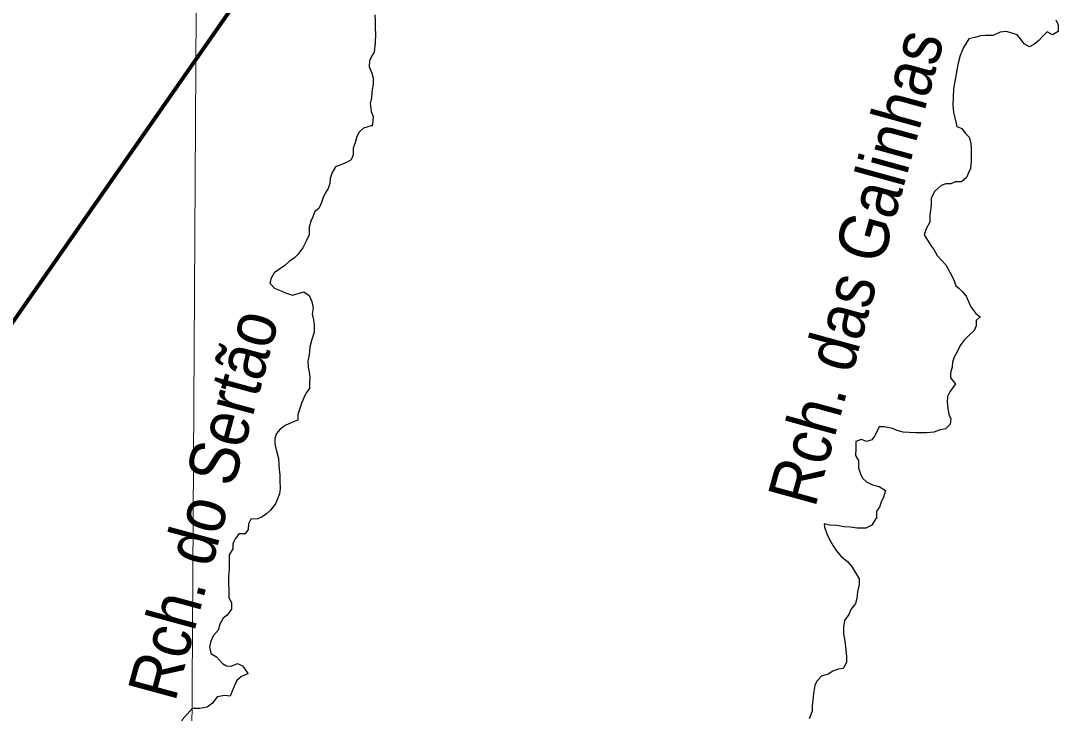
# Model space of a CAD drawing. Extents: x 553962 to 842807, y 8883888 to 9032388.
# Drawn here: x 717768 to 728228, y 8938163 to 8945147 of the extents above; entities that cross this region are included whole.
import ezdxf
from ezdxf.enums import TextEntityAlignment as Align

# ---------------------------------------------------------------- set-up
doc = ezdxf.new("R2010")
doc.units = 0
doc.header["$LTSCALE"] = 200
for name, color, linetype, lineweight in [('1', 7, 'Continuous', 13), ('24', 7, 'Continuous', 25), ('28', 7, 'Continuous', 40)]:
    doc.layers.add(name, color=color, linetype=linetype, lineweight=lineweight)
doc.layers.add('49', color=7, linetype='Continuous')

msp = doc.modelspace()

# ---------------------------------------------------------------- linework, layer by layer
at = {"layer": '1'}
msp.add_lwpolyline([(719978.9, 9023574.5), (719561.6, 8949232.2), (719215.6, 8890710.6)], dxfattribs=at)
at = {"layer": '24'}
for points in [[(728203.3, 8945156.8), (728228.4, 8945105.7), (728228, 8945039.5), (728171.8, 8945004.2), (728116, 8945035.1), (728069.9, 8944989.6), (728034.1, 8944949), (727982.9, 8944908.6), (727937, 8944883.4), (727886.3, 8944914.3), (727851, 8944960.3), (727815.8, 8945006.4), (727765, 8945022), (727704.1, 8945037.6), (727643, 8945032.9), (727571.6, 8944997.7), (727495.3, 8944998.2), (727444.4, 8944993.4), (727388.3, 8944978.4), (727327.2, 8944963.6), (727273, 8944875.7), (727239.5, 8944797.4), (727239.5, 8944797.4), (727217.1, 8944704.3), (727172.4, 8944462.1)], [(721333.1, 8944831.8), (721314, 8944802.2), (721283.1, 8944746.3), (721282.7, 8944685.2), (721307.7, 8944618.9), (721322.6, 8944567.9), (721322.1, 8944506.8), (721306.3, 8944425.4), (721305.9, 8944369.4), (721290.3, 8944313.4), (721299.9, 8944231.9), (721319.9, 8944180.8), (721319.5, 8944129.9), (721309.9, 8944083.2)], [(727172.4, 8944462.1), (727164.9, 8944294.4), (727172.4, 8944223.6), (727194.7, 8944123), (727205.5, 8944081.4), (727256.2, 8944060.7), (727291.5, 8944014.6), (727331.9, 8943973.7), (727346.8, 8943912.4), (727351.5, 8943856.4), (727351.1, 8943800.4), (727350.6, 8943729.1), (727345, 8943657.8), (727324.3, 8943612.1), (727303.7, 8943566.4), (727252.5, 8943520.9), (727191.5, 8943521.3), (727145.6, 8943501.2), (727094.7, 8943501.5), (727048.8, 8943486.5), (726982.3, 8943425.8), (726946.2, 8943354.7), (726945.7, 8943288.5), (726940.3, 8943237.7), (726934.9, 8943186.8), (726934.4, 8943115.5), (726898.3, 8943049.5), (726877.6, 8942988.5), (726942.9, 8942881.2), (726973.2, 8942840.2), (727008.3, 8942778.9), (727094.2, 8942686.7), (727159.5, 8942569.2), (727179.5, 8942523.2), (727194.4, 8942472.2)], [(721311.4, 8944090.8), (721222.4, 8944064.3), (721181.5, 8944023.8), (721155.7, 8943978.2), (721140.1, 8943917.2), (721119.3, 8943861.3), (721118.9, 8943795.1), (721098.2, 8943744.3), (721052.2, 8943719.1), (720996.1, 8943694), (720940, 8943673.9), (720909.1, 8943618.1), (720888.3, 8943557.1), (720882.9, 8943506.2), (720867.3, 8943455.4), (720836.5, 8943409.8), (720815.8, 8943364.1), (720800.2, 8943313.2), (720774.3, 8943252.3), (720733.5, 8943222), (720712.8, 8943171.2), (720692.1, 8943125.5), (720676.4, 8943064.5), (720675.9, 8942988.1), (720650.1, 8942932.2), (720613.9, 8942856.1), (720562.6, 8942790.2), (720526.8, 8942754.7), (720475.7, 8942719.4), (720429.6, 8942678.9), (720368.3, 8942633.5), (720322.3, 8942603.2), (720291.4, 8942552.5), (720280.9, 8942501.6), (720326.3, 8942450.4), (720377, 8942429.8), (720437.9, 8942403.9), (720508.9, 8942378), (720565, 8942398), (720621, 8942413), (720676.7, 8942377), (720701.7, 8942315.7), (720716.5, 8942249.4), (720706, 8942188.4), (720720.8, 8942132.3), (720725.5, 8942076.2), (720725, 8942004.9), (720704.2, 8941933.8), (720683.3, 8941857.5), (720677.7, 8941776.1), (720662, 8941715.1), (720666.7, 8941653.9), (720676.5, 8941602.9), (720681.2, 8941552), (720680.8, 8941501.1), (720680.4, 8941440), (720644.5, 8941394.3), (720623.8, 8941343.6), (720603.2, 8941297.8), (720582.4, 8941236.9), (720561.6, 8941175.9), (720561.2, 8941119.9), (720500, 8941094.8), (720433.7, 8941064.6), (720382.6, 8941029.3), (720346.7, 8940983.7), (720331.1, 8940932.9), (720330.7, 8940881.9), (720345.5, 8940805.5), (720365.3, 8940734), (720370, 8940672.9), (720374.7, 8940621.9), (720379.4, 8940565.9), (720379, 8940509.9), (720383.5, 8940428.4), (720378.1, 8940377.5), (720336.7, 8940275.9), (720285.4, 8940210), (720244.5, 8940174.6), (720203.6, 8940144.3), (720157.6, 8940124.2), (720086.4, 8940119.6), (720065.7, 8940073.9), (720060.3, 8940017.9), (720029.4, 8939972.2), (719968.4, 8939972.6), (719932.5, 8939927), (719906.7, 8939876.2), (719906.3, 8939820.2), (719870.3, 8939759.3), (719869.9, 8939703.3), (719869.3, 8939611.7), (719863.7, 8939545.5), (719863.2, 8939464), (719867.9, 8939408), (719867.3, 8939326.5), (719892.4, 8939280.5), (719892, 8939214.3), (719850.8, 8939153.5), (719810, 8939123.2), (719773.9, 8939062.3)], [(727194.4, 8942472.2), (727224.8, 8942451.7), (727260.1, 8942415.8), (727300.5, 8942369.7), (727345.5, 8942262.5), (727395.9, 8942196), (727441.4, 8942160.1), (727443.2, 8942160.1)], [(727441.4, 8942160.1), (727400.5, 8942124.7), (727400.1, 8942068.7), (727379.5, 8942023), (727328.2, 8941972.3), (727277, 8941921.7), (727241.1, 8941871), (727205, 8941800), (727179.2, 8941754.3), (727163.6, 8941703.5), (727158.2, 8941652.6), (727142.6, 8941596.7), (727142.2, 8941545.7), (727187.6, 8941489.4), (727193.7, 8941485.1)], [(727194.1, 8941484.8), (727136.1, 8941403.2), (727110.4, 8941357.5), (727110, 8941301.5), (727114.6, 8941235.3), (727124.4, 8941179.2), (727144.4, 8941133.2), (727139, 8941077.2), (727092.9, 8941031.7), (727026.7, 8941016.8), (726975.7, 8940996.8), (726904.4, 8940992.1), (726853.6, 8940992.4), (726792.5, 8940992.8), (726726.4, 8940993.2), (726665.4, 8940998.7), (726604.5, 8941014.3), (726558.9, 8941035), (726472.5, 8941050.8), (726421.7, 8941051.1), (726380.3, 8940959.7), (726349.5, 8940919.1), (726298.6, 8940904.2), (726242.8, 8940924.9), (726186.7, 8940904.8), (726186.2, 8940833.6), (726185.7, 8940762.3), (726215.9, 8940711.2), (726215.4, 8940639.9), (726235.3, 8940578.6), (726255.3, 8940532.7), (726295.8, 8940496.8), (726356.6, 8940465.9), (726422.6, 8940450.2), (726488.4, 8940409), (726467.6, 8940343), (726441.8, 8940292.2), (726426.2, 8940241.4), (726395.4, 8940200.8), (726394.9, 8940125.5)], [(726388.5, 8940126.2), (726348.7, 8940058.5), (726287.4, 8940028.3), (726201, 8940028.9), (726134.9, 8940039.4), (726068.8, 8940044.9), (725997.7, 8940055.6), (725921.5, 8940061.1), (725866.7, 8940073.8), (725866.7, 8940073.8)], [(725866.7, 8940074.6), (725866.7, 8940073.8), (725872.8, 8940040.7), (725897.7, 8939964.2), (725932.8, 8939897.8), (725957.9, 8939851.8), (725988.1, 8939805.8), (726043.6, 8939739.2), (726104.3, 8939693), (726149.7, 8939636.7), (726179.9, 8939585.6), (726220.1, 8939519.2), (726219.7, 8939463.2), (726203.9, 8939386.9), (726198.4, 8939320.7), (726182.8, 8939269.9), (726136.6, 8939209.1), (726115.9, 8939158.2), (726074.8, 8939097.4), (726064.2, 8939031.3), (726063.7, 8938960), (726073.5, 8938909), (726088, 8938807.1), (726092.6, 8938730.6), (726092.2, 8938674.6), (726061.2, 8938613.7), (726010.4, 8938608.9), (725954.3, 8938588.9), (725908.3, 8938558.6), (725842, 8938538.7), (725795.9, 8938488)], [(719773.9, 8939062.3), (719758.2, 8939001.2), (719707, 8938945.6), (719686.3, 8938889.7), (719670.6, 8938833.7), (719685.4, 8938767.4), (719741.1, 8938731.5), (719801.7, 8938664.9), (719844, 8938640.7), (719890.2, 8938638.6), (719890.2, 8938638.6)], [(719890.2, 8938638.6), (719953.8, 8938664.2), (720004.3, 8938640.4), (720024.2, 8938614.6), (720058.9, 8938563), (720061.4, 8938559.7)], [(720060.8, 8938559.8), (720055.8, 8938559.8), (719994.6, 8938534.7), (719948.5, 8938494.2), (719922.7, 8938443.5), (719881.3, 8938336.8), (719825.4, 8938342.2), (719749, 8938327.4), (719702.8, 8938266.6), (719646.6, 8938226.2), (719575.3, 8938211.3), (719495.9, 8938211.8)], [(725795.9, 8938488), (725775.3, 8938442.3), (725759.4, 8938360.9), (725753.9, 8938294.8), (725748.4, 8938238.8), (725748, 8938182.8), (725717, 8938106.6)], [(719495.9, 8938211.8), (719394.7, 8938096.4), (719328.4, 8937863.4), (719342.1, 8937802.6), (719401.1, 8937732.2), (719437, 8937644.3), (719483.8, 8937567.5), (719487.5, 8937545.9), (719449.3, 8937492.5), (719434.6, 8937455.6), (719420.2, 8937279.4), (719367.4, 8937201.3), (719297.2, 8937190.5), (719130.2, 8937185.6)]]:
    msp.add_lwpolyline(points, dxfattribs=at)
msp.add_spline([(721338.8, 8945205.7), (721343, 8945051.6), (721343, 8944957), (721332, 8944830.1)], degree=3, dxfattribs=at)
at = {"layer": '28', "lineweight": 80}
msp.add_lwpolyline([(720171.2, 8945676.6), (715086.9, 8938383.2), (711274.8, 8933762.2), (707980.3, 8932086.5)], dxfattribs=at)

# ---------------------------------------------------------------- texts
at = {"layer": '49', "width": 0.9}
for s, rotation, p in [('Rch. das Galinhas', 74.592, (726429.3, 8942595.9)), ('Rch. do Sertão', 74.808, (719849.9, 8940205))]:
    msp.add_text(s, height=500, rotation=rotation, dxfattribs=at).set_placement(p, align=Align.CENTER)

doc.saveas('drawing.dxf')
